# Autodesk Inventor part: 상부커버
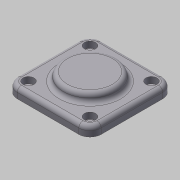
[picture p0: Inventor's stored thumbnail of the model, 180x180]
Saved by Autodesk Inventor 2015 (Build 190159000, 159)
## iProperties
Created: 2018-09
Part Number: 상부커버
Document SubType Name: Modeling
Density: 2.71 g/cm^3
Material: 알루미늄 6061
Mass: 115.577 g
Surface Area: 104.357 cm^2
Volume: 42.6483 cm^3
Appearance: 알루미늄 - 평지
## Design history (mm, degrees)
sketch "스케치1"
  geometry: L1 (30, 22)-(30, -22); L2 (-22, 30)-(22, 30); L3 (-30, -22)-(-30, 22); L4 (22, -30)-(-22, -30); L5 (-30, 0)-(30, 0); L6 (0, 30)-(0, -30); C1 r 20 at (0, 0); A1 r 8 centre (22, 22) between (30, 22) and (22, 30); A2 r 8 centre (-22, 22) between (-22, 30) and (-30, 22); A3 r 8 centre (-22, -22) between (-30, -22) and (-22, -30); A4 r 8 centre (22, -22) between (22, -30) and (30, -22); 2 further points
  constraints: 12 end point, 8 point on circle, 7 midpoint, 7 tangent, 5 centre point, 3 equal radius, 2 horizontal, 1 coincident, 1 vertical
  dimensions: "d23" = 60 distance between parallel lines of L1 L3; "d25" = 60 distance between parallel lines of L4 L2; "d26" = 8 radius of A2; "d27" = 40 diameter of C1
extrude "돌출1" new body sketch "스케치1" distance "d0" = 7; taper "d1" = 0 deg
extrude "돌출2" join sketch "스케치1" distance "d2" = 10; taper "d3" = 0 deg
sketch "스케치2"
  geometry: C1 r 19 at (0, 0); 1 further point
  constraints: 1 centre point, 1 coincident
  dimensions: "d4" = 38 diameter of C1
extrude "돌출3" join sketch "스케치2" distance "d5" = 6; taper "d6" = 0 deg
fillet "모깎기1" dims "d7" = 3
fillet "모깎기2" dims "d8" = 3
sketch "스케치4"
  geometry: L1 (30, 22)-(30, -22) reference; L2 (-22, 30)-(22, 30) reference; L3 (-30, -22)-(-30, 22) reference; L4 (22, -30)-(-22, -30) reference; C1 r 22 at (0, 0) reference; A1 r 8 centre (-22, 22) between (-22, 30) and (-30, 22) reference; A2 r 8 centre (22, 22) between (30, 22) and (22, 30) reference; A3 r 8 centre (-22, 22) between (-22, 30) and (-30, 22) reference; A4 r 8 centre (-22, -22) between (-30, -22) and (-22, -30) reference; A5 r 8 centre (22, -22) between (22, -30) and (30, -22) reference; 5 further points
  constraints: 4 coincident
hole "구멍2" sketch "스케치4" at (-22, 22), (22, 22), (22, -22), (-22, -22) diameter "d28" = 4.5; stored, may be unused: countersink angle "d32" = 90 deg, drill point angle "d34" = 118 deg; dims "d29" = 6, "d30" = 8, "d31" = 4.5, "d33" = 8
fillet "모깎기3" dims "d19" = 3
chamfer "모따기1" distance "d20" = 1; stored, may be unused: second distance "d21" = 2, angle "d22" = 45 deg
node "솔리드1"
node "투영된 루프1"
